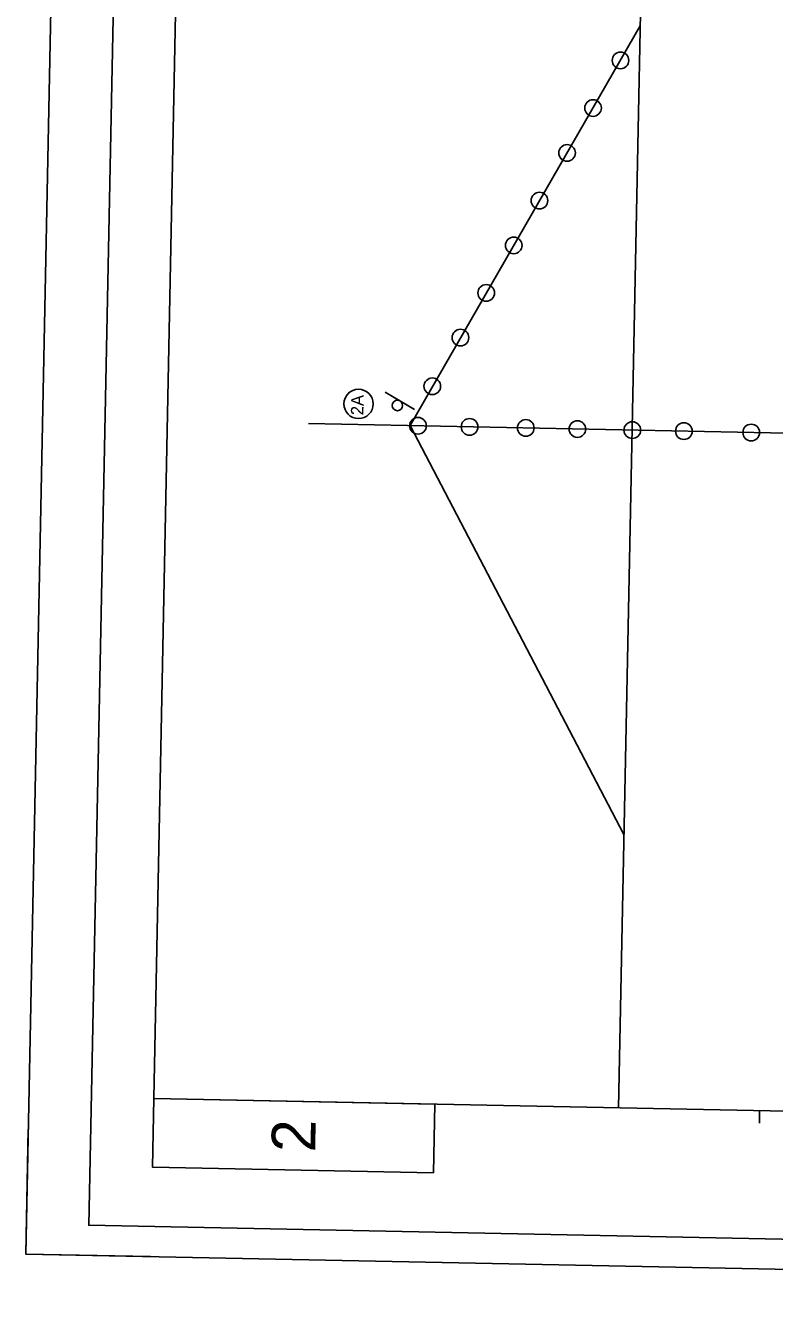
# Model space of a CAD drawing. Extents: x 345549 to 379569, y 127949 to 230467.
# Drawn here: x 345549 to 354537, y 178813 to 194223 of the extents above; entities that cross this region are included whole.
import ezdxf

# ---------------------------------------------------------------- set-up
doc = ezdxf.new("R2010")
doc.units = 0
for name, color, linetype in [('CA-TEXT', 7, 'Continuous'), ('CE-TOPO-CONC-SLAB', 7, 'Continuous'), ('E_RDWY', 7, 'Continuous'), ('P_RDWY_Text', 7, 'Continuous'), ('PLT_Sheet_Border', 7, 'Continuous'), ('PLT_Sheet_Info', 7, 'Continuous'), ('SIGNS-POLES', 7, 'Continuous')]:
    doc.layers.add(name, color=color, linetype=linetype)

msp = doc.modelspace()

# ---------------------------------------------------------------- linework, layer by layer
at = {"layer": 'CA-TEXT'}
msp.add_circle((349545, 189683), 176, dxfattribs=at)
at = {"layer": 'CE-TOPO-CONC-SLAB'}
for centre in [(352690, 193807), (352360, 193235), (352048, 192695), (351717, 192123), (351408, 191586), (351078, 191015), (350769, 190478), (350431, 189894), (350259, 189420), (350878, 189407), (351553, 189394), (352172, 189381), (352832, 189368), (353451, 189356), (354259, 189339)]:
    msp.add_circle(centre, 100, dxfattribs=at)
at = {"layer": 'E_RDWY'}
for p, q in [((352666, 181232), (353388, 217082)), ((350166, 189422), (352927, 194223)), ((359265, 189238), (348946, 189446)), ((350166, 189422), (352732, 184513))]:
    msp.add_line(p, q, dxfattribs=at)
at = {"layer": 'P_RDWY_Text'}
msp.add_lwpolyline([(345549, 179477), (346576, 230467), (379569, 229803), (378542, 178813)], close=True, dxfattribs=at)
at = {"layer": 'PLT_Sheet_Border'}
for points in [[(378542, 178813), (379569, 229803), (346576, 230467), (345549, 179477)], [(377800, 179188), (378799, 228828), (347306, 229462), (346306, 179822)]]:
    msp.add_lwpolyline(points, close=True, dxfattribs=at)
at = {"layer": 'PLT_Sheet_Info'}
for p, q in [((347087, 181344), (348038, 228585)), ((377081, 180740), (347087, 181344)), ((354360, 181198), (354357, 181048)), ((345549, 179477), (345579, 180977)), ((347049, 179447), (345549, 179477))]:
    msp.add_line(p, q, dxfattribs=at)
msp.add_lwpolyline([(347087, 181344), (347070, 180520), (350445, 180452), (350461, 181276)], close=True, dxfattribs=at)
at = {"layer": 'SIGNS-POLES'}
for p, q in [((349865, 189822), (350041, 189721)), ((350041, 189719), (350216, 189617))]:
    msp.add_line(p, q, dxfattribs=at)
msp.add_circle((350012, 189664), 62.6, dxfattribs=at)

# ---------------------------------------------------------------- texts
at = {"layer": 'CA-TEXT'}
msp.add_text('2A', height=150, rotation=88.8468, dxfattribs=at).set_placement((349603, 189545))
at = {"layer": 'PLT_Sheet_Info'}
msp.add_text('2', height=525, rotation=88.8462, dxfattribs=at).set_placement((349024, 180696))

doc.saveas('drawing.dxf')
